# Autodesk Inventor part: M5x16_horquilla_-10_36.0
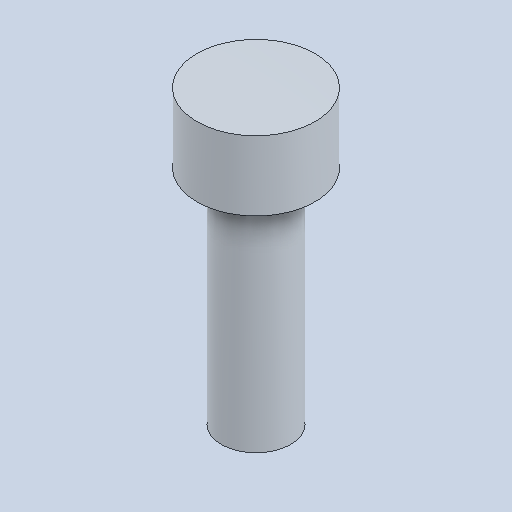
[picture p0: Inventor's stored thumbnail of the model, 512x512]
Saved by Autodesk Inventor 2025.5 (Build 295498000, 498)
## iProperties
Created: 2026-10
Part Number: M5x16_horquilla_-10_36.0
Material: Genérico
Document SubType Name: Modeling
Designer: Luis M
Density: 1 g/cm^3
Appearance: Valor por defecto
Author: Luis M
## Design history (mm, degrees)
feature "Base1"
node "Sólido1"
